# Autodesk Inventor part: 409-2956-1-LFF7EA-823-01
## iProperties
Created: 2010-11
Part Number: 409-2956-1-LFF7EA-823-01
Material: 3/8" OD TUBE - SS
Document SubType Name: Modeling
Designer: S. Boerckel
Engineer: Steve Boerckel
Mass: 314.256 g
Surface Area: 681.145 cm^2
Volume: 38.893 cm^3
Density: 8.08 g/cm^3
Description: PRESSURE DIFF TUBE
Length: 76.588 in
Author: S. Boerckel
Revision Number: 0
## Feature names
1. Sweep2
